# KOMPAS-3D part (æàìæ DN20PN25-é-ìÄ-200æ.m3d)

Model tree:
1. Объединить компоненты:1  (labels: СЕНС DN20PN25-В-НО-200С)

Referenced files in D:\Савин\!СЕНСОР\3D для заказчика\!Новый перечень\СЕНС\7. СЕНС-В-НО-200С\DN20\: СЕНС DN20PN25-В-НО-200С.a3d
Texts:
  СЕНС DN20PN25-В-НО-200С
  ООО НПП Сенсор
